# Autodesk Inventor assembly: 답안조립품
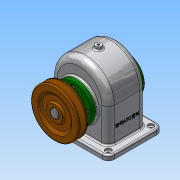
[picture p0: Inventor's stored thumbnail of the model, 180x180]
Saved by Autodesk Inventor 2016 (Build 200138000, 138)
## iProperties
Created: 2018-08
Part Number: 답안조립품
Material: 일반
Document SubType Name: Assembly
Designer: Administrator
Author: Administrator
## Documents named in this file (14)
- C:\Users\Administrator\Desktop\480811V1010\답안조립품.iam
- C:\Users\Administrator\Desktop\480811V1010\본체.ipt
- C:\Users\Administrator\Desktop\480811V1010\베어링 6203.ipt
- C:\Users\Administrator\Desktop\480811V1010\뒤커버.ipt
- C:\Users\Administrator\Desktop\480811V1010\볼트 M4.ipt
- C:\Users\Administrator\Desktop\480811V1010\축.ipt
- C:\Users\Administrator\Desktop\480811V1010\키 6x6x22.ipt
- C:\Users\Administrator\Desktop\480811V1010\스퍼기어.ipt
- C:\Users\Administrator\Desktop\480811V1010\앞커버.ipt
- C:\Users\Administrator\Desktop\480811V1010\키 5x5x18.ipt
- C:\Users\Administrator\Desktop\480811V1010\오일 실 28 40 8.ipt
- C:\Users\Administrator\Desktop\480811V1010\부시.ipt
- C:\Users\Administrator\Desktop\480811V1010\V-벨트풀리.ipt
- C:\Users\Administrator\Desktop\480811V1010\멈춤나사 M4.ipt
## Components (1 placed, 1 different names)
1. V-벨트풀리:2
